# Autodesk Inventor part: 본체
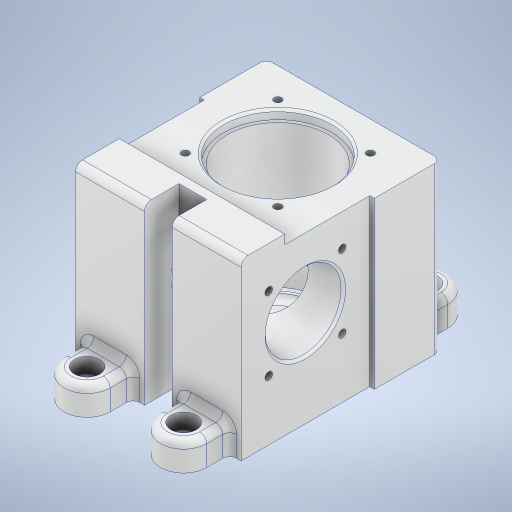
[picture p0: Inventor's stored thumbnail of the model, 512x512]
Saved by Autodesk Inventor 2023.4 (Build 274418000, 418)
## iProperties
Created: 2024-11
Part Number: 본체
Material: 알루미늄 6061
Document SubType Name: Modeling
Designer: EDU-001
Mass: 869.258 g
Surface Area: 555.311 cm^2
Volume: 321.947 cm^3
Density: 2.7 g/cm^3
Appearance: 알루미늄 - 평지
Author: EDU-001
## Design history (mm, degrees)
sketch "스케치1"
  geometry: L1 (0, 0)-(-72, 0); L2 (-72, 0)-(-72, -56); L3 (-72, -56)-(0, -56); L4 (0, -56)-(0, 0); L5 (2, -56)-(-74, -56); L6 (-74, -56)-(-74, -85); L7 (-74, -85)-(2, -85); L8 (2, -85)-(2, -56); 2 further points
  constraints: 16 end point, 4 parallel, 2 horizontal, 2 perpendicular
  dimensions: "d2" = 72 distance of L3.end L2.end; "d3" = 56 distance of L2.end L1.end; "d4" = 76 distance of L6.end L7.end; "d5" = 2 distance between parallel lines of L4 L8; "d6" = 29 distance between parallel lines of L5 L7; "d7" = 85 distance between parallel lines of L1 L7
extrude "돌출1" new body sketch "스케치1" distance "d8" = 72; taper "d9" = 0 deg
sketch "스케치2"
  geometry: L1 (0, 0)-(72, 0) reference; L2 (0, 0)-(72, 0); L3 (72, 0)-(72, 19); L4 (72, 19)-(0, 19); L5 (0, 19)-(0, 0); L6 (74, 85)-(-2, 85) reference; 3 further points
  constraints: 8 end point, 2 parallel, 1 horizontal, 1 midpoint, 1 perpendicular, 1 vertical alignment
  dimensions: "d10" = 66 distance between parallel lines of L4 L6
extrude "돌출2" join sketch "스케치2" distance "d11" = 4; taper "d12" = 0 deg
node "작업 평면1"
sketch "스케치4"
  geometry: L1 (2, -56)-(0, -56) reference; L2 (2, -56)-(0, -56) reference; L3 (2, -85)-(2, -56) reference; L4 (2, -85)-(2, -56) reference; L5 (0, -56)-(0, -19) reference; L6 (0, -56)-(0, 0) reference; L7 (0, 0)-(-72, 0) reference; L8 (-72, -56)-(-74, -56) reference; L9 (-74, -85)-(2, -85) reference; L10 (-74, -85)-(2, -85) reference; L11 (-74, -56)-(-74, -85) reference; L12 (0, -19)-(0, 0) reference; L13 (0, -19)-(-72, -19) reference; L14 (-72, -19)-(0, -19) reference; L15 (0, 0)-(-72, 0) reference; L16 (-72, -19)-(-72, -56) reference; L17 (-72, 0)-(-72, -56) reference; L18 (-72, 0)-(-72, -19) reference; L19 (-72, -56)-(-74, -56) reference; L20 (-74, -56)-(-74, -85) reference; L21 (-57, -75)-(-57, -95); L22 (-67, -75)-(-67, -95); L23 (-47, -95)-(-47, -75); L24 (-15, -75)-(-15, -95); L25 (-25, -75)-(-25, -95); L26 (-5, -95)-(-5, -75); L27 (-36, -85)-(-36, 0); L28 (-57, 10)-(-57, -10); L29 (-67, 10)-(-67, -10); L30 (-47, -10)-(-47, 10); L31 (-15, 10)-(-15, -10); L32 (-25, 10)-(-25, -10); L33 (-5, -10)-(-5, 10); A1 r 10 centre (-57, -75) between (-47, -75) and (-67, -75); A2 r 10 centre (-57, -95) between (-67, -95) and (-47, -95); A3 r 10 centre (-15, -75) between (-5, -75) and (-25, -75); A4 r 10 centre (-15, -95) between (-25, -95) and (-5, -95); A5 r 10 centre (-57, 10) between (-47, 10) and (-67, 10); A6 r 10 centre (-57, -10) between (-67, -10) and (-47, -10); A7 r 10 centre (-15, 10) between (-5, 10) and (-25, 10); A8 r 10 centre (-15, -10) between (-25, -10) and (-5, -10); 14 further points
  constraints: 34 end point, 16 point on circle, 16 tangent, 8 centre point, 8 midpoint, 6 parallel, 4 perpendicular, 4 point on line, 2 horizontal alignment, 2 other
  dimensions: "d15" = 20 diameter of A2; "d16" = 20 diameter of A4; "d17" = 10 distance from line of L9 L21.end; "d18" = 42 distance of L24.end L21.end; "d19" = 20 diameter of A6; "d20" = 20 diameter of A8; "d21" = 42 distance between parallel lines of L31 L28; "d22" = 10 distance of L31.start point (-15, 0)
extrude "돌출3" join sketch "스케치4" distance "d23" = 12; taper "d24" = 0 deg
sketch "스케치5"
  geometry: L1 (0, 0)-(72, 0) reference; L2 (30, 0)-(42, 0); L3 (42, 0)-(42, 15); L4 (42, 15)-(30, 15); L5 (30, 15)-(30, 0); L6 (47, 85)-(25, 85) reference; L7 (36, 85)-(36, 0); 1 further point
  constraints: 10 end point, 2 midpoint, 2 parallel, 2 perpendicular, 1 horizontal, 1 point on line, 1 other
  dimensions: "d25" = 15 distance between parallel lines of L1 L4; "d26" = 12 distance of L3.end L4.end
extrude "돌출4" cut sketch "스케치5" extent not by distance; stored distance "d27" = 0; taper "d28" = 0 deg
node "작업 평면2"
sketch "스케치6"
  geometry: L1 (52, -2.702)-(52, 94.86); L2 (85, 0)-(85, 72) reference; L3 (85, 72)-(56, 72) reference; L4 (75.5, 72)-(75.5, 68); L5 (75.5, 68)-(74, 68); L6 (74, 68)-(74, 20); L7 (74, 20)-(69.5, 20); L8 (69.5, 20)-(69.5, 9); L9 (69.5, 9)-(67, 9); L10 (67, 9)-(67, 6); L11 (67, 6)-(52, 6); L12 (19, 76)-(0, 76) reference; L13 (75.5, 72)-(52, 72); 2 further points
  constraints: 20 end point, 7 perpendicular, 3 point on line, 2 vertical, 1 horizontal
  dimensions: "d29" = 33 distance between parallel lines of L1 L2; "d30" = 47 diameter of L4 L1; "d31" = 44 diameter of L6 L1; "d32" = 35 diameter of L8 L1; "d33" = 30 diameter of L10 L1; "d34" = 3 distance of L9.end L10.end; "d35" = 11 distance of L7.end L8.end; "d36" = 4 distance of L4.start L4.end; "d37" = 56 distance between parallel lines of L12 L7
revolve "회전1" sketch "스케치6" stored, may be unused: angle "d38" = 90 deg
sketch "스케치7"
  geometry: L1 (56, 0)-(0, 0) reference; L2 (-29, 0)-(-29, 72) reference; C1 r 16.5 at (28, 42)
  constraints: 1 centre point
  dimensions: "d39" = 33 diameter of C1; "d40" = 42 distance from line of L1 C1.centre; "d41" = 57 distance from line of C1.centre L2
extrude "돌출5" cut sketch "스케치7" extent not by distance; stored distance "d42" = 0; taper "d43" = 0 deg
sketch "스케치8"
  geometry: A1 r 10 centre (15, -10) between (5, -10) and (25, -10) reference; 2 further points
  constraints: 1 coincident
hole "구멍1" sketch "스케치8" at (15, -10) diameter "d44" = 6.6; stored, may be unused: countersink angle "d48" = 90 deg, drill point angle "d50" = 118 deg; dims "d45" = 6, "d46" = 11, "d47" = 6.6, "d49" = 8
node "작업 평면4"
node "작업 평면5"
fillet "모깎기1" dims "d51" = 3
fillet "모깎기2" dims "d52" = 3
fillet "모깎기3" dims "d53" = 3
chamfer "모따기1" distance "d54" = 1; stored, may be unused: second distance "d55" = 2, angle "d56" = 45 deg
fillet "모깎기4" dims "d57" = 3
fillet "모깎기5" dims "d58" = 0.6
fillet "모깎기6" dims "d59" = 3
sketch "스케치9"
  geometry: L1 (36, 52)-(36, 80.5); L2 (36, 52)-(56.153, 72.153); C1 r 15.6 at (36, 52) reference; A1 r 28.5 centre (36, 52) between (36, 80.5) and (56.153, 72.153); 2 further points
  constraints: 4 end point, 2 coincident, 2 point on circle, 1 centre point, 1 vertical
  dimensions: "d60" = 57 diameter of A1; "d61" = 45 deg angle of L2 L1
hole "구멍2" sketch "스케치9" at (56.153, 72.153) diameter "d62" = 3.242; stored, may be unused: countersink angle "d66" = 90 deg, drill point angle "d68" = 118 deg; dims "d63" = 8, "d64" = 11, "d65" = 6.6, "d67" = 10
sketch "스케치10"
  geometry: L1 (0, 0)-(56, 0) reference; C1 r 16.5 at (28, 42) reference; 4 further points
  constraints: 5 other
  dimensions: "d72" = 58 distance from line of L1 point (44, 58); "d73" = 16 horizontal distance of point (44, 58) C1.centre; "d76" = 360 deg dimension on C1.centre point (44, 58) (derived)
hole "구멍3" sketch "스케치10" at (44, 58), (12, 58), (12, 26), (44, 26) diameter "d78" = 3.242; stored, may be unused: countersink angle "d82" = 90 deg, drill point angle "d84" = 118 deg; dims "d79" = 8, "d80" = 4, "d81" = 2, "d83" = 10
node "작업 평면6"
sketch "스케치11"
  geometry: L1 (0, 0)-(16, 0) reference; L2 (-27, 72)-(43, 72) reference; L3 (8, 72)-(8, 0); 3 further points
  constraints: 3 midpoint, 2 end point, 1 vertical alignment, 1 other
  dimensions: "d85" = 20 distance from line of L2 point (8, 52)
feature "엠보싱1" sketch "스케치11" dims "d2" = 72, "d3" = 56, "d4" = 76, "d5" = 2, "d6" = 29, "d7" = 85, "d86" = 0.5, "d87" = 0
sketch "스케치12"
  geometry: L1 (42, 76)-(-30, 76) reference; L2 (6, 76)-(6, 0); L3 (14, 0)-(-2, 0) reference; L4 (12, 0)-(0, 0) reference; 4 further points
  constraints: 3 midpoint, 2 end point, 1 point on line, 1 vertical alignment
  dimensions: "d88" = 12 distance from line of L1 point (6, 64); "d89" = 40 distance of point (6, 24) point (6, 64)
hole "구멍4" sketch "스케치12" at (6, 64), (6, 24) diameter "d90" = 3.242; stored, may be unused: countersink angle "d94" = 90 deg, drill point angle "d96" = 118 deg; dims "d91" = 8, "d92" = 4, "d93" = 2, "d95" = 10
chamfer "모따기2" distance "d97" = 1; stored, may be unused: second distance "d98" = 2, angle "d99" = 45 deg
fillet "모깎기7" dims "d100" = 3
chamfer "모따기3" distance "d101" = 1; stored, may be unused: second distance "d102" = 2, angle "d103" = 45 deg
feature "΢耀Τ耀Φ耀Ψ耀Ϊ耀ά耀ή耀ΰ耀" dims "d2" = 72, "d3" = 56, "d4" = 76, "d5" = 2, "d6" = 29, "d7" = 85, "d8" = 72, "d9" = 0, "d10" = 66, "d11" = 4, "d12" = 0, "d15" = 20, "d16" = 20, "d17" = 10, "d18" = 42, "d19" = 20, "d20" = 20, "d21" = 42, "d22" = 10, "d23" = 12, "d24" = 0, "d25" = 15, "d26" = 12, "d27" = 0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
node "솔리드1"
mirror "미러2"
mirror "미러3"
pattern_circular "원형 패턴1" dims angle "d70" = 360 deg
mirror "미러4"
feature "A9D066F2-1C7D-4E18-AEED-F7BC21143FA4" dims "d62" = 3.242, "d63" = 8, "d64" = 11, "d65" = 6.6, "d66" = 90 deg, "d67" = 10, "d68" = 118 deg
